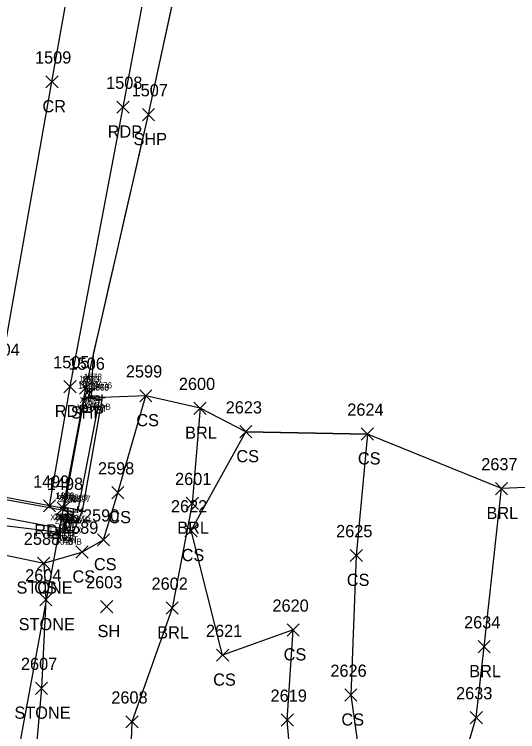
# Model space of a CAD drawing. Extents: x 1472022 to 1479249, y 777216 to 786527.
# Drawn here: x 1473740.7 to 1473823.2, y 779767.2 to 779884.8 of the extents above; entities that cross this region are included whole.
import ezdxf

# ---------------------------------------------------------------- set-up
doc = ezdxf.new("R2010")
doc.units = 0
for name, color, linetype in [('B_A', 7, 'Continuous'), ('B_I', 7, 'Continuous'), ('B_TIC', 7, 'Continuous'), ('BELB', 7, 'Continuous'), ('BSE', 7, 'Continuous'), ('BSUBM', 7, 'Continuous'), ('L_A', 7, 'Continuous'), ('L_I', 7, 'Continuous'), ('L_TIC', 7, 'Continuous'), ('LABL', 7, 'Continuous'), ('LASF', 7, 'Continuous'), ('LELB', 7, 'Continuous'), ('LSOGP', 7, 'Continuous'), ('P_A', 7, 'Continuous'), ('P_I', 7, 'Continuous'), ('P_TIC', 7, 'Continuous'), ('PET', 7, 'Continuous'), ('PRC', 7, 'Continuous'), ('PSP', 7, 'Continuous')]:
    doc.layers.add(name, color=color, linetype=linetype)

msp = doc.modelspace()

# ---------------------------------------------------------------- linework, layer by layer
at = {"layer": 'B_TIC'}
for p, q in [((1473752.71, 779823.1), (1473752.78, 779823.1)), ((1473753.44, 779823.41), (1473753.51, 779823.41)), ((1473752.25, 779821.91), (1473752.32, 779821.91)), ((1473752.96, 779822.04), (1473753.03, 779822.04)), ((1473753.06, 779822.99), (1473753.13, 779822.99)), ((1473753.37, 779822.27), (1473753.44, 779822.27)), ((1473755.14, 779822), (1473755.21, 779822)), ((1473755.14, 779822), (1473755.21, 779822)), ((1473754.61, 779821.63), (1473754.69, 779821.63)), ((1473754.61, 779821.63), (1473754.69, 779821.63)), ((1473754.62, 779821.7), (1473754.69, 779821.7)), ((1473754.62, 779821.7), (1473754.69, 779821.7)), ((1473748.74, 779803.86), (1473748.81, 779803.86)), ((1473748.96, 779803.94), (1473749.03, 779803.94)), ((1473749.42, 779803.44), (1473749.5, 779803.44)), ((1473749.53, 779803.42), (1473749.61, 779803.42)), ((1473749.53, 779803.42), (1473749.61, 779803.42)), ((1473750.39, 779803.24), (1473750.47, 779803.24)), ((1473750.39, 779803.24), (1473750.47, 779803.24)), ((1473751.15, 779803.61), (1473751.22, 779803.61)), ((1473751.86, 779803.39), (1473751.93, 779803.39)), ((1473751.86, 779803.39), (1473751.93, 779803.39)), ((1473748.9, 779800.48), (1473748.98, 779800.48)), ((1473748.9, 779800.48), (1473748.98, 779800.48)), ((1473748.98, 779799.83), (1473749.06, 779799.83)), ((1473749.03, 779800.46), (1473749.1, 779800.46)), ((1473749.85, 779800.22), (1473749.93, 779800.22)), ((1473750.39, 779799.88), (1473750.46, 779799.88))]:
    msp.add_line(p, q, dxfattribs=at)
for points in [[(1473752.21, 779823.1), (1473753.21, 779823.1)], [(1473752.71, 779822.6), (1473752.71, 779823.6)], [(1473752.93, 779823.41), (1473753.93, 779823.41)], [(1473753.05, 779822.49), (1473753.05, 779823.49)], [(1473753.43, 779822.91), (1473753.43, 779823.91)], [(1473751.74, 779821.91), (1473752.74, 779821.91)], [(1473752.24, 779821.41), (1473752.24, 779822.41)], [(1473752.45, 779822.04), (1473753.45, 779822.04)], [(1473752.55, 779822.99), (1473753.55, 779822.99)], [(1473752.86, 779822.27), (1473753.86, 779822.27)], [(1473752.95, 779821.54), (1473752.95, 779822.54)], [(1473753.36, 779821.77), (1473753.36, 779822.77)], [(1473754.61, 779821.2), (1473754.61, 779822.2)], [(1473754.61, 779821.2), (1473754.61, 779822.2)], [(1473754.61, 779821.13), (1473754.61, 779822.13)], [(1473754.61, 779821.13), (1473754.61, 779822.13)], [(1473754.63, 779822), (1473755.63, 779822)], [(1473754.63, 779822), (1473755.63, 779822)], [(1473755.13, 779821.5), (1473755.13, 779822.5)], [(1473755.13, 779821.5), (1473755.13, 779822.5)], [(1473754.11, 779821.7), (1473755.11, 779821.7)], [(1473754.11, 779821.7), (1473755.11, 779821.7)], [(1473754.11, 779821.63), (1473755.11, 779821.63)], [(1473754.11, 779821.63), (1473755.11, 779821.63)], [(1473748.73, 779803.36), (1473748.73, 779804.36)], [(1473748.95, 779803.44), (1473748.95, 779804.44)], [(1473748.23, 779803.86), (1473749.23, 779803.86)], [(1473748.45, 779803.94), (1473749.45, 779803.94)], [(1473748.92, 779803.44), (1473749.92, 779803.44)], [(1473749.03, 779803.42), (1473750.03, 779803.42)], [(1473749.03, 779803.42), (1473750.03, 779803.42)], [(1473749.42, 779802.94), (1473749.42, 779803.94)], [(1473749.53, 779802.92), (1473749.53, 779803.92)], [(1473749.53, 779802.92), (1473749.53, 779803.92)], [(1473749.89, 779803.24), (1473750.89, 779803.24)], [(1473749.89, 779803.24), (1473750.89, 779803.24)], [(1473750.39, 779802.74), (1473750.39, 779803.74)], [(1473750.39, 779802.74), (1473750.39, 779803.74)], [(1473750.64, 779803.61), (1473751.64, 779803.61)], [(1473751.14, 779803.11), (1473751.14, 779804.11)], [(1473751.35, 779803.39), (1473752.35, 779803.39)], [(1473751.35, 779803.39), (1473752.35, 779803.39)], [(1473751.85, 779802.89), (1473751.85, 779803.89)], [(1473751.85, 779802.89), (1473751.85, 779803.89)], [(1473748.9, 779799.98), (1473748.9, 779800.98)], [(1473748.9, 779799.98), (1473748.9, 779800.98)], [(1473749.03, 779799.96), (1473749.03, 779800.96)], [(1473749.85, 779799.72), (1473749.85, 779800.72)], [(1473748.4, 779800.48), (1473749.4, 779800.48)], [(1473748.4, 779800.48), (1473749.4, 779800.48)], [(1473748.48, 779799.83), (1473749.48, 779799.83)], [(1473748.53, 779800.46), (1473749.53, 779800.46)], [(1473748.98, 779799.33), (1473748.98, 779800.33)], [(1473749.35, 779800.22), (1473750.35, 779800.22)], [(1473749.88, 779799.88), (1473750.88, 779799.88)], [(1473750.38, 779799.38), (1473750.38, 779800.38)]]:
    msp.add_lwpolyline(points, dxfattribs=at)
at = {"layer": 'BELB'}
msp.add_lwpolyline([(1473748.73, 779803.86), (1473737.38, 779742.92)], dxfattribs=at)
at = {"layer": 'BSE'}
for points in [[(1473718.78, 779809.03), (1473718.28, 779806.2), (1473748.9, 779800.48)], [(1473718.78, 779809.03), (1473749.42, 779803.44), (1473748.9, 779800.48)]]:
    msp.add_lwpolyline(points, dxfattribs=at)
at = {"layer": 'BSUBM'}
for points in [[(1473719.87, 779828.55), (1473716.36, 779809.73), (1473716.54, 779806.01), (1473719.57, 779805.21), (1473727.45, 779803.32), (1473739.11, 779801.02), (1473748.98, 779799.83), (1473750.38, 779799.88), (1473751.85, 779803.39)], [(1473754.61, 779821.63), (1473751.14, 779803.61), (1473748.95, 779803.94), (1473752.24, 779821.91), (1473752.71, 779823.1), (1473753.05, 779822.99), (1473752.95, 779822.04), (1473754.61, 779821.7)], [(1473753.43, 779823.41), (1473752.42, 779823.56)], [(1473755.13, 779822), (1473753.36, 779822.27), (1473753.43, 779823.41)], [(1473755.13, 779822), (1473751.85, 779803.39)], [(1473754.61, 779821.63), (1473754.61, 779821.7)], [(1473749.53, 779803.42), (1473749.03, 779800.46), (1473749.85, 779800.22), (1473750.39, 779803.24)], [(1473749.53, 779803.42), (1473750.39, 779803.24)]]:
    msp.add_lwpolyline(points, dxfattribs=at)
at = {"layer": 'L_TIC'}
for points in [[(1473761.27, 779821.29), (1473763.27, 779823.29)], [(1473763.27, 779821.29), (1473761.27, 779823.29)], [(1473770.17, 779819.24), (1473772.17, 779821.24)], [(1473772.17, 779819.24), (1473770.17, 779821.24)], [(1473777.68, 779815.39), (1473779.68, 779817.39)], [(1473779.68, 779815.39), (1473777.68, 779817.39)], [(1473797.61, 779815.02), (1473799.61, 779817.02)], [(1473799.61, 779815.02), (1473797.61, 779817.02)], [(1473819.59, 779806.07), (1473821.59, 779808.07)], [(1473821.59, 779806.07), (1473819.59, 779808.07)], [(1473756.68, 779805.39), (1473758.68, 779807.39)], [(1473758.68, 779805.39), (1473756.68, 779807.39)], [(1473768.89, 779803.65), (1473770.89, 779805.65)], [(1473770.89, 779803.65), (1473768.89, 779805.65)], [(1473768.69, 779799.17), (1473770.69, 779801.17)], [(1473770.69, 779799.17), (1473768.69, 779801.17)], [(1473754.32, 779797.67), (1473756.32, 779799.67)], [(1473756.32, 779797.67), (1473754.32, 779799.67)], [(1473750.8, 779795.66), (1473752.8, 779797.66)], [(1473752.8, 779795.66), (1473750.8, 779797.66)], [(1473795.78, 779795.1), (1473797.78, 779797.1)], [(1473797.78, 779795.1), (1473795.78, 779797.1)], [(1473744.52, 779793.84), (1473746.52, 779795.84)], [(1473746.52, 779793.84), (1473744.52, 779795.84)], [(1473744.52, 779793.84), (1473746.52, 779795.84)], [(1473746.52, 779793.84), (1473744.52, 779795.84)], [(1473744.88, 779787.84), (1473746.88, 779789.84)], [(1473746.88, 779787.84), (1473744.88, 779789.84)], [(1473754.86, 779786.71), (1473756.86, 779788.71)], [(1473756.86, 779786.71), (1473754.86, 779788.71)], [(1473765.6, 779786.48), (1473767.6, 779788.48)], [(1473767.6, 779786.48), (1473765.6, 779788.48)], [(1473785.43, 779782.88), (1473787.43, 779784.88)], [(1473787.43, 779782.88), (1473785.43, 779784.88)], [(1473816.76, 779780.14), (1473818.76, 779782.14)], [(1473818.76, 779780.14), (1473816.76, 779782.14)], [(1473773.87, 779778.74), (1473775.87, 779780.74)], [(1473775.87, 779778.74), (1473773.87, 779780.74)], [(1473744.17, 779773.32), (1473746.17, 779775.32)], [(1473746.17, 779773.32), (1473744.17, 779775.32)], [(1473794.9, 779772.2), (1473796.9, 779774.2)], [(1473796.9, 779772.2), (1473794.9, 779774.2)], [(1473815.46, 779768.51), (1473817.46, 779770.51)], [(1473817.46, 779768.51), (1473815.46, 779770.51)], [(1473759, 779767.82), (1473761, 779769.82)], [(1473761, 779767.82), (1473759, 779769.82)], [(1473784.47, 779768.11), (1473786.47, 779770.11)], [(1473786.47, 779768.11), (1473784.47, 779770.11)]]:
    msp.add_lwpolyline(points, dxfattribs=at)
at = {"layer": 'LABL'}
msp.add_lwpolyline([(1473771.17, 779820.24), (1473769.89, 779804.65), (1473766.6, 779787.48), (1473760, 779768.82), (1473759.46, 779755.41), (1473760.69, 779730.5), (1473785.64, 779730.39), (1473804.65, 779742.56), (1473812.09, 779754.63), (1473816.46, 779769.51), (1473817.76, 779781.14), (1473820.59, 779807.07)], dxfattribs=at)
at = {"layer": 'LASF'}
msp.add_lwpolyline([(1473674.63, 779812.66), (1473674.49, 779800.35), (1473673.09, 779784.2), (1473672.47, 779768.8), (1473686.21, 779764.41), (1473701.45, 779761.38), (1473708.8, 779772.85), (1473712.08, 779786.76), (1473716.54, 779806.01), (1473719.24, 779801.78), (1473727.32, 779798.69), (1473745.52, 779794.84), (1473745.88, 779788.84), (1473745.17, 779774.32), (1473743.47, 779755.08), (1473741.69, 779728.71)], dxfattribs=at)
at = {"layer": 'LELB'}
for points in [[(1473745.52, 779794.84), (1473751.8, 779796.66), (1473755.32, 779798.67), (1473757.68, 779806.39), (1473762.27, 779822.29)], [(1473785.64, 779730.39), (1473785.75, 779741.77), (1473786.52, 779756.7), (1473785.47, 779769.11), (1473786.43, 779783.88), (1473774.87, 779779.74), (1473769.69, 779800.17), (1473778.68, 779816.39), (1473798.61, 779816.02), (1473796.78, 779796.1), (1473795.9, 779773.2), (1473797.55, 779761.56), (1473804.65, 779742.56)]]:
    msp.add_lwpolyline(points, dxfattribs=at)
at = {"layer": 'LSOGP'}
msp.add_lwpolyline([(1473841.42, 779807.94), (1473820.59, 779807.07), (1473798.61, 779816.02), (1473778.68, 779816.39), (1473771.17, 779820.24), (1473762.27, 779822.29), (1473755.13, 779822), (1473754.25, 779822.14), (1473753.36, 779822.27), (1473753.43, 779823.41), (1473753.71, 779829.17), (1473755, 779834.77), (1473756.28, 779840.38), (1473757.57, 779845.98), (1473758.85, 779851.59), (1473760.14, 779857.19), (1473761.42, 779862.8), (1473762.71, 779868.4), (1473764.29, 779875.72), (1473765.86, 779883.03), (1473767.44, 779890.35)], dxfattribs=at)
at = {"layer": 'P_TIC'}
for points in [[(1473745.88, 779872.78), (1473747.88, 779874.78)], [(1473747.88, 779872.78), (1473745.88, 779874.78)], [(1473757.54, 779868.63), (1473759.54, 779870.63)], [(1473759.54, 779868.63), (1473757.54, 779870.63)], [(1473761.71, 779867.4), (1473763.71, 779869.4)], [(1473763.71, 779867.4), (1473761.71, 779869.4)], [(1473748.84, 779822.79), (1473750.84, 779824.79)], [(1473750.84, 779822.79), (1473748.84, 779824.79)], [(1473751.42, 779822.56), (1473753.42, 779824.56)], [(1473753.42, 779822.56), (1473751.42, 779824.56)], [(1473745.48, 779803.23), (1473747.48, 779805.23)], [(1473747.48, 779803.23), (1473745.48, 779805.23)], [(1473745.48, 779803.23), (1473747.48, 779805.23)], [(1473747.48, 779803.23), (1473745.48, 779805.23)], [(1473747.73, 779802.86), (1473749.73, 779804.86)], [(1473749.73, 779802.86), (1473747.73, 779804.86)], [(1473747.73, 779802.86), (1473749.73, 779804.86)], [(1473749.73, 779802.86), (1473747.73, 779804.86)]]:
    msp.add_lwpolyline(points, dxfattribs=at)
at = {"layer": 'PET'}
for points in [[(1473746.48, 779804.23), (1473735, 779806.45), (1473719.43, 779809.21), (1473722.68, 779826.96), (1473722.64, 779829.09), (1473731.65, 779877.71), (1473741.4, 779933.53), (1473746.83, 779966.3), (1473755, 780011.96), (1473766.14, 780070.64), (1473776.66, 780127.43), (1473786.78, 780182.03), (1473796.49, 780236.66), (1473805.8, 780286.73), (1473813.14, 780328.66), (1473818.03, 780354.99), (1473826.83, 780403.57), (1473832.05, 780432.32), (1473842.07, 780489.82), (1473851.78, 780539.26), (1473858.97, 780579.12), (1473867.36, 780624.13)], [(1473748.73, 779803.86), (1473746.48, 779804.23), (1473749.84, 779823.79), (1473758.54, 779869.63), (1473769.57, 779928.11), (1473775.61, 779960.49), (1473783.9, 780007.6), (1473794.95, 780065.64), (1473805.21, 780123.07), (1473815.24, 780176.97), (1473825.12, 780231.74), (1473834.38, 780281.06), (1473842, 780323.35), (1473851.32, 780373.06), (1473861.15, 780428.07), (1473871.31, 780483.08), (1473880.48, 780535.96), (1473887.71, 780574.3), (1473895.6, 780618.75)]]:
    msp.add_lwpolyline(points, dxfattribs=at)
at = {"layer": 'PRC'}
msp.add_lwpolyline([(1473735, 779806.45), (1473738.41, 779825.86), (1473746.88, 779873.78), (1473757.16, 779931.4), (1473763.53, 779963.46), (1473771.55, 780009.55), (1473781.83, 780068.07), (1473792.3, 780125.59), (1473802.3, 780178.66), (1473811.81, 780233.39), (1473821.47, 780283.6), (1473828.72, 780325.68), (1473837.7, 780374.01), (1473847.63, 780429.6), (1473858, 780486.03), (1473867.42, 780537.6), (1473874.56, 780576.61), (1473882.64, 780621.02)], dxfattribs=at)
at = {"layer": 'PSP'}
msp.add_lwpolyline([(1473748.73, 779803.86), (1473752.42, 779823.56), (1473762.71, 779868.4), (1473775.32, 779926.92), (1473782.16, 779958.6), (1473792.83, 780005.65), (1473803.68, 780063.67), (1473813.75, 780121.6), (1473823.74, 780173.97), (1473833.9, 780230.35), (1473842.97, 780280.28), (1473850.64, 780321.91), (1473860.15, 780373.2), (1473869.95, 780426.63), (1473880.31, 780480.63), (1473890.06, 780534.18), (1473897.21, 780573.03), (1473905.39, 780617.74)], dxfattribs=at)

# ---------------------------------------------------------------- texts
at = {"layer": 'B_A'}
for s, p in [('XAT', (1473751.41, 779821.1)), ('XAT', (1473751.76, 779820.99)), ('XAB', (1473752.15, 779821.41)), ('XAT', (1473750.95, 779819.91)), ('XAT', (1473751.66, 779820.04)), ('XAB', (1473752.09, 779820.27)), ('XAB', (1473753.85, 779820)), ('XAB', (1473753.85, 779820)), ('XAT', (1473753.31, 779819.63)), ('XAT', (1473753.31, 779819.63)), ('XAT', (1473753.32, 779819.7)), ('XAT', (1473753.32, 779819.7)), ('XDECK', (1473746.58, 779801.86)), ('XAT', (1473747.66, 779801.94)), ('XBS', (1473748.16, 779801.44)), ('XAT', (1473748.24, 779801.42)), ('XAT', (1473748.24, 779801.42)), ('XAT', (1473749.09, 779801.24)), ('XAT', (1473749.09, 779801.24)), ('XAT', (1473749.85, 779801.61)), ('XAB', (1473750.57, 779801.39)), ('XAB', (1473750.57, 779801.39)), ('XBS', (1473747.64, 779798.48)), ('XBS', (1473747.64, 779798.48)), ('XAB', (1473747.7, 779797.83)), ('XAT', (1473747.73, 779798.46)), ('XAT', (1473748.55, 779798.22)), ('XAB', (1473749.1, 779797.88))]:
    msp.add_text(s, height=1, dxfattribs=at).set_placement(p)
at = {"layer": 'B_I'}
for s, p in [('1872', (1473751.36, 779824.6)), ('1873', (1473751.71, 779824.49)), ('1878', (1473752.09, 779824.91)), ('1871', (1473751.18, 779823.41)), ('1874', (1473751.61, 779823.54)), ('1877', (1473752.02, 779823.77)), ('1876', (1473753.76, 779823.5)), ('1876', (1473753.76, 779823.5)), ('1868', (1473753.24, 779823.13)), ('1868', (1473753.24, 779823.13)), ('1875', (1473753.27, 779823.2)), ('1875', (1473753.27, 779823.2)), ('1498', (1473747.39, 779805.36)), ('1870', (1473747.56, 779805.44)), ('2825', (1473747.79, 779804.94)), ('2591', (1473748.18, 779804.92)), ('2591', (1473748.18, 779804.92)), ('2594', (1473748.76, 779804.74)), ('2594', (1473748.76, 779804.74)), ('1869', (1473749.77, 779805.11)), ('2597', (1473750.22, 779804.89)), ('2597', (1473750.22, 779804.89)), ('2826', (1473747.24, 779801.98)), ('2826', (1473747.24, 779801.98)), ('2595', (1473747.35, 779801.33)), ('2592', (1473747.4, 779801.96)), ('2593', (1473748.22, 779801.72)), ('2596', (1473748.73, 779801.38))]:
    msp.add_text(s, height=1, dxfattribs=at).set_placement(p)
at = {"layer": 'L_A'}
for s, p in [('CS', (1473760.71, 779817.29)), ('BRL', (1473768.71, 779815.24)), ('CS', (1473777.12, 779811.39)), ('CS', (1473797.05, 779811.02)), ('CS', (1473756.12, 779801.39)), ('BRL', (1473818.14, 779802.07)), ('BRL', (1473767.43, 779799.65)), ('CS', (1473768.14, 779795.17)), ('CS', (1473753.76, 779793.67)), ('CS', (1473750.24, 779791.66)), ('CS', (1473795.23, 779791.1)), ('STONE', (1473741.06, 779789.84)), ('CS', (1473743.96, 779789.84)), ('STONE', (1473741.42, 779783.84)), ('SH', (1473754.35, 779782.71)), ('BRL', (1473764.14, 779782.48)), ('CS', (1473784.87, 779778.88)), ('BRL', (1473815.31, 779776.14)), ('CS', (1473773.31, 779774.74)), ('STONE', (1473740.72, 779769.32)), ('CS', (1473794.34, 779768.2))]:
    msp.add_text(s, height=2, dxfattribs=at).set_placement(p)
at = {"layer": 'L_I'}
for s, p in [('2599', (1473759, 779825.29)), ('2600', (1473767.69, 779823.24)), ('2623', (1473775.37, 779819.39)), ('2624', (1473795.31, 779819.02)), ('2598', (1473754.42, 779809.39)), ('2637', (1473817.28, 779810.07)), ('2601', (1473767.07, 779807.65)), ('2622', (1473766.39, 779803.17)), ('2590', (1473751.97, 779801.67)), ('2589', (1473748.53, 779799.66)), ('2625', (1473793.48, 779799.1)), ('2588', (1473742.26, 779797.84)), ('2588', (1473742.26, 779797.84)), ('2604', (1473742.49, 779791.84)), ('2603', (1473752.47, 779790.71)), ('2602', (1473763.21, 779790.48)), ('2620', (1473783.04, 779786.88)), ('2634', (1473814.46, 779784.14)), ('2621', (1473772.13, 779782.74)), ('2607', (1473741.79, 779777.32)), ('2626', (1473792.54, 779776.2)), ('2608', (1473756.61, 779771.82)), ('2619', (1473782.73, 779772.11)), ('2633', (1473813.15, 779772.51))]:
    msp.add_text(s, height=2, dxfattribs=at).set_placement(p)
at = {"layer": 'P_A'}
for s, p in [('CR', (1473745.31, 779868.78)), ('RDP', (1473756.02, 779864.63)), ('SHP', (1473760.25, 779863.4)), ('RDP', (1473747.33, 779818.79)), ('SHP', (1473749.96, 779818.56)), ('RDP', (1473743.97, 779799.23)), ('RDP', (1473743.97, 779799.23)), ('SHP', (1473746.27, 779798.86)), ('RDP', (1473746.22, 779798.86))]:
    msp.add_text(s, height=2, dxfattribs=at).set_placement(p)
at = {"layer": 'P_I'}
for s, p in [('1509', (1473744.1, 779876.78)), ('1508', (1473755.76, 779872.63)), ('1507', (1473759.94, 779871.4)), ('1504', (1473735.64, 779828.86)), ('1505', (1473747.07, 779826.79)), ('1506', (1473749.6, 779826.56)), ('1499', (1473743.78, 779807.23)), ('1499', (1473743.78, 779807.23)), ('1498', (1473746.04, 779806.86)), ('1498', (1473746.04, 779806.86))]:
    msp.add_text(s, height=2, dxfattribs=at).set_placement(p)

doc.saveas('drawing.dxf')
